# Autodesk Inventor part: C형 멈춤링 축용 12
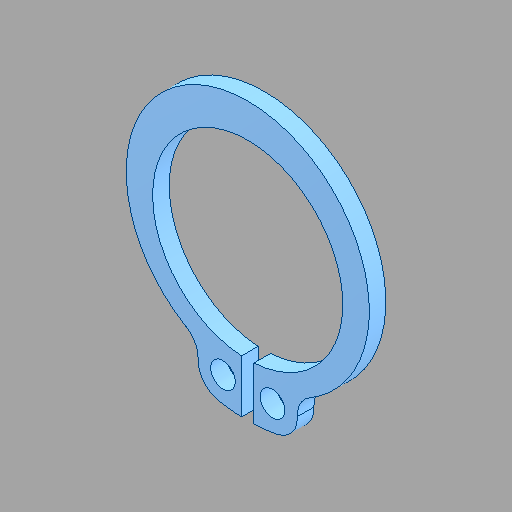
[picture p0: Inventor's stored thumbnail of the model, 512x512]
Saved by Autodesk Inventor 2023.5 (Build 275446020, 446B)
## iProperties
Created: 2026-03
Part Number: C형 멈춤링 축용 12
Material: 강철, 연강
Description: 리테이닝 링(C형)
Document SubType Name: Modeling
Designer: mirae
Density: 7.85 g/cm^3
Appearance: 기본값
Author: jhkim
Sending System: Autodesk Inventor 2026
Preprocessor: ST-DEVELOPER v20.1
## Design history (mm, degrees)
node "C형 멈춤링 축용 121"
node "솔리드1"
body "Solid1"
